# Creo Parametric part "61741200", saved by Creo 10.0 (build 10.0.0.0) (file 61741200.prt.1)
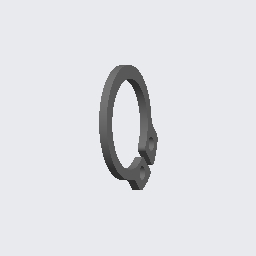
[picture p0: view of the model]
Units: millimeter Newton Second (mmNs); MM, TONNE, SECS

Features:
  1. coordinate system "61741200"
  2. imported feature "Import-ke ID 4"

Other named items: NOTE_0

Notes: 61741200

Surfaces: 16 cylinder, 6 plane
